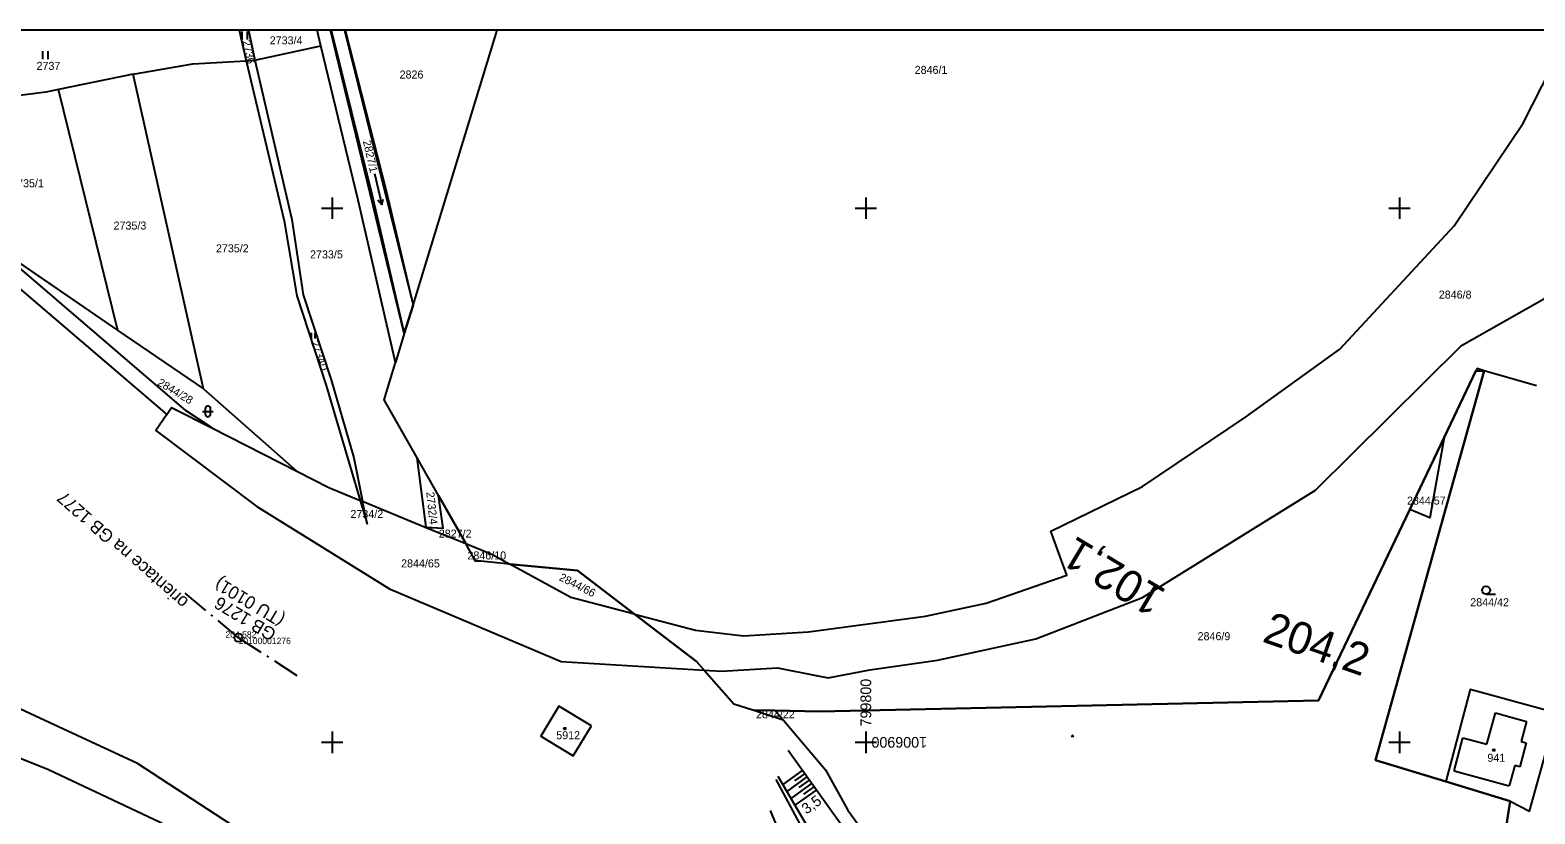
# Model space of a CAD drawing. Extents: x -800194 to -799078, y -1007177 to -1006597.
# Drawn here: x -799956.6 to -799674.6, y -1006913.4 to -1006766.6 of the extents above; entities that cross this region are included whole.
import ezdxf

# ---------------------------------------------------------------- set-up
doc = ezdxf.new("R2010")
doc.units = 0
for name, color, linetype in [('_Vrstva 7 - Přesunutá', 7, 'Continuous'), ('Legenda 1', 7, 'Continuous'), ('Ramove udaje', 7, 'Continuous'), ('Vrstva 48', 7, 'Continuous'), ('Vrstva 49', 7, 'Continuous'), ('Vrstva 53', 7, 'Continuous'), ('Vrstva 55', 7, 'Continuous'), ('Vrstva 56', 7, 'Continuous'), ('Vrstva 57', 7, 'Continuous'), ('Vrstva 58', 7, 'Continuous'), ('Vrstva 59', 7, 'Continuous'), ('Vrstva 60', 7, 'Continuous'), ('Vrstva 61', 7, 'Continuous'), ('Vrstva 63', 7, 'Continuous'), ('Vrstva 7', 7, 'Continuous')]:
    doc.layers.add(name, color=color, linetype=linetype)

msp = doc.modelspace()

# ---------------------------------------------------------------- linework, layer by layer
at = {"layer": 'Legenda 1'}
msp.add_lwpolyline([(-800193.4, -1007176.65), (-799312.4, -1007176.65), (-799312.4, -1006766.65), (-800193.4, -1006766.65)], close=True, dxfattribs=at)
at = {"layer": 'Ramove udaje'}
for p, q in [((-799900, -1006798), (-799900, -1006802)), ((-799800, -1006798), (-799800, -1006802)), ((-799700, -1006798), (-799700, -1006802)), ((-799902, -1006800), (-799900, -1006800)), ((-799900, -1006800), (-799898, -1006800)), ((-799802, -1006800), (-799800, -1006800)), ((-799800, -1006800), (-799798, -1006800)), ((-799702, -1006800), (-799700, -1006800)), ((-799700, -1006800), (-799698, -1006800)), ((-799900, -1006898), (-799900, -1006902)), ((-799800, -1006898), (-799800, -1006902)), ((-799700, -1006898), (-799700, -1006902)), ((-799902, -1006900), (-799900, -1006900)), ((-799900, -1006900), (-799898, -1006900)), ((-799802, -1006900), (-799800, -1006900)), ((-799800, -1006900), (-799798, -1006900)), ((-799702, -1006900), (-799700, -1006900)), ((-799700, -1006900), (-799698, -1006900))]:
    msp.add_line(p, q, dxfattribs=at)
at = {"layer": 'Vrstva 48'}
for p, q in [((-799811.93, -1006905.27), (-799815.58, -1006907.89)), ((-799811.05, -1006906.49), (-799814.82, -1006909.19)), ((-799811.49, -1006905.88), (-799813.35, -1006907.21)), ((-799810.18, -1006907.71), (-799814.06, -1006910.49)), ((-799809.31, -1006908.93), (-799813.3, -1006911.79)), ((-799810.62, -1006907.1), (-799812.53, -1006908.47)), ((-799809.74, -1006908.32), (-799811.71, -1006909.73))]:
    msp.add_line(p, q, dxfattribs=at)
at = {"layer": 'Vrstva 49'}
for p, q in [((-799761.44, -1006898.59), (-799761.08, -1006898.95)), ((-799761.44, -1006898.95), (-799761.08, -1006898.59))]:
    msp.add_line(p, q, dxfattribs=at)
for points in [[(-799779.16, -1006943.33), (-799796.9, -1006926.25), (-799814.58, -1006901.56)], [(-799816.48, -1006906.34), (-799809.08, -1006919.03), (-799804.33, -1006925.79)], [(-799804.93, -1006926.45), (-799809.53, -1006920.44), (-799816.79, -1006906.94)], [(-799817.93, -1006912.77), (-799815.19, -1006919.41), (-799811.75, -1006925.64), (-799808.12, -1006930.68), (-799809.62, -1006932.5), (-799809.74, -1006938.63), (-799809.9, -1006941.36)]]:
    msp.add_lwpolyline(points, dxfattribs=at)
at = {"layer": 'Vrstva 53'}
for points in [[(-799897.71, -1006766.65), (-799884.86, -1006818.16), (-799886.49, -1006823.47), (-799900.34, -1006766.65)], [(-799963.94, -1006806.68), (-799940.15, -1006822.89), (-799924.15, -1006833.79), (-799906.63, -1006849.24), (-799900.66, -1006852.28), (-799894.78, -1006854.69), (-799894.32, -1006854.87), (-799882.56, -1006859.69), (-799879.2, -1006859.87), (-799880.09, -1006853.81), (-799874.98, -1006862.8), (-799869.94, -1006864.86), (-799866.71, -1006866.63), (-799854.06, -1006867.84), (-799843.37, -1006876), (-799831.75, -1006884.86), (-799830.3, -1006886.5), (-799824.73, -1006892.78), (-799821.02, -1006893.98), (-799817.05, -1006894.06), (-799808.6, -1006894.22), (-799715.17, -1006892.15), (-799698.08, -1006856.38), (-799691.64, -1006842.91), (-799685.69, -1006830.46), (-799684.1, -1006830.47), (-799704.46, -1006903.31), (-799691.31, -1006907.33), (-799679.26, -1006911.01), (-799685.71, -1006952.41)], [(-799673.33, -1007118.14), (-799714.71, -1007110.97), (-799718.21, -1007083.69), (-799729.93, -1007087.54), (-799766.47, -1007095.84), (-799767.73, -1007094.8), (-799769.22, -1007093.56), (-799785.06, -1007080.42), (-799809.11, -1007056.81), (-799818.59, -1007034.4), (-799822.79, -1007029.13), (-799826.14, -1007024.13), (-799830.75, -1006966.73), (-799839.73, -1006961.33), (-799877.87, -1006942.17), (-799936.47, -1006903.99), (-799954.76, -1006895.45), (-799964.79, -1006890.84)]]:
    msp.add_lwpolyline(points, dxfattribs=at)
at = {"layer": 'Vrstva 55'}
for p, q in [((-799917.43, -1006766.65), (-799916.1, -1006772.38)), ((-799915.71, -1006766.65), (-799914.5, -1006772.29)), ((-799902.13, -1006769.59), (-799902.84, -1006766.65)), ((-799884.86, -1006818.16), (-799869.08, -1006766.65)), ((-799914.5, -1006772.29), (-799902.13, -1006769.59)), ((-799895.13, -1006798.48), (-799902.13, -1006769.59)), ((-799916.1, -1006772.38), (-799914.5, -1006772.29)), ((-799937.29, -1006774.9), (-799951.32, -1006777.78)), ((-799924.15, -1006833.79), (-799937.29, -1006774.9)), ((-799953.68, -1006778.26), (-799969.88, -1006780.37)), ((-799951.32, -1006777.78), (-799953.68, -1006778.26)), ((-799940.15, -1006822.89), (-799951.32, -1006777.78)), ((-799888.13, -1006828.86), (-799895.13, -1006798.48)), ((-799963.94, -1006806.68), (-799940.15, -1006822.89)), ((-799965.36, -1006809.25), (-799930.99, -1006838.59)), ((-799886.49, -1006823.47), (-799884.86, -1006818.16)), ((-799940.15, -1006822.89), (-799924.15, -1006833.79)), ((-799886.49, -1006823.47), (-799888.13, -1006828.86)), ((-799685.69, -1006830.46), (-799691.64, -1006842.91)), ((-799674.35, -1006833.26), (-799684.1, -1006830.47)), ((-799924.15, -1006833.79), (-799906.63, -1006849.24)), ((-799922.45, -1006841.18), (-799906.63, -1006849.24)), ((-799691.64, -1006842.91), (-799698.08, -1006856.38)), ((-799882.39, -1006859.7), (-799884.1, -1006846.76)), ((-799880.09, -1006853.81), (-799884.1, -1006846.76)), ((-799894.78, -1006854.69), (-799894.32, -1006854.87)), ((-799894.32, -1006854.87), (-799882.56, -1006859.69)), ((-799874.98, -1006862.8), (-799880.09, -1006853.81)), ((-799698.08, -1006856.38), (-799715.17, -1006892.15)), ((-799882.56, -1006859.69), (-799882.39, -1006859.7)), ((-799882.56, -1006859.69), (-799874.98, -1006862.8)), ((-799817.05, -1006894.06), (-799821.02, -1006893.98)), ((-799821.02, -1006893.98), (-799815.49, -1006895.78)), ((-799817.05, -1006894.06), (-799815.49, -1006895.78)), ((-799679.26, -1006911.01), (-799691.31, -1006907.33))]:
    msp.add_line(p, q, dxfattribs=at)
for points in [[(-799900.21, -1006766.65), (-799892.52, -1006797.61), (-799886.49, -1006823.47)], [(-799897.57, -1006766.65), (-799889.91, -1006796.74), (-799884.86, -1006818.16)], [(-799843.37, -1006876), (-799831.92, -1006878.98), (-799822.92, -1006880.05), (-799810.74, -1006879.32), (-799788.82, -1006876.36), (-799777.45, -1006873.96), (-799762.31, -1006868.73), (-799765.35, -1006860.47), (-799748.13, -1006852.13), (-799728.87, -1006839.09), (-799711.19, -1006826.38), (-799689.75, -1006803.29), (-799676.83, -1006784.06), (-799667.97, -1006766.65)], [(-799830.3, -1006886.5), (-799827.05, -1006886.7), (-799816.55, -1006886.06), (-799808.97, -1006887.52), (-799807.07, -1006887.91), (-799799.23, -1006886.45), (-799786.57, -1006884.64), (-799768.13, -1006880.63), (-799748.15, -1006872.9), (-799715.76, -1006852.76), (-799688.4, -1006825.67), (-799672.84, -1006816.93), (-799646.34, -1006766.65)], [(-799937.29, -1006774.9), (-799926.1, -1006772.97), (-799916.1, -1006772.38)], [(-799916.1, -1006772.38), (-799909.03, -1006802.36), (-799906.63, -1006816.4), (-799901.12, -1006833.19), (-799894.78, -1006854.69)], [(-799914.5, -1006772.29), (-799907.57, -1006802.13), (-799905.43, -1006816.22), (-799900.18, -1006832.12), (-799895.95, -1006846.75), (-799894.32, -1006854.87)], [(-799922.45, -1006841.18), (-799927.36, -1006837.92), (-799963.94, -1006806.68)], [(-799884.1, -1006846.76), (-799890.29, -1006835.89), (-799888.13, -1006828.86)], [(-799684.1, -1006830.47), (-799685.46, -1006829.98), (-799685.69, -1006830.46)], [(-799691.31, -1006907.33), (-799704.46, -1006903.31), (-799684.1, -1006830.47)], [(-799930.99, -1006838.59), (-799933.07, -1006841.6), (-799914.11, -1006855.86), (-799889.24, -1006871.28), (-799857.12, -1006884.86), (-799830.3, -1006886.5)], [(-799930.99, -1006838.59), (-799930.09, -1006837.28), (-799922.45, -1006841.18)], [(-799691.64, -1006842.91), (-799694.3, -1006857.94), (-799698.08, -1006856.38)], [(-799906.63, -1006849.24), (-799900.66, -1006852.28), (-799894.78, -1006854.69)], [(-799894.78, -1006854.69), (-799893.48, -1006859.09), (-799894.32, -1006854.87)], [(-799882.39, -1006859.7), (-799879.2, -1006859.87), (-799880.09, -1006853.81)], [(-799874.98, -1006862.8), (-799869.94, -1006864.86), (-799866.71, -1006866.63)], [(-799866.71, -1006866.63), (-799872.12, -1006866.11), (-799873.12, -1006866.06), (-799874.98, -1006862.8)], [(-799843.37, -1006876), (-799855.29, -1006872.89), (-799866.71, -1006866.63)], [(-799843.37, -1006876), (-799854.06, -1006867.84), (-799866.71, -1006866.63)], [(-799830.3, -1006886.5), (-799831.75, -1006884.86), (-799843.37, -1006876)], [(-799830.3, -1006886.5), (-799824.73, -1006892.78), (-799821.02, -1006893.98)], [(-799901.69, -1006974.63), (-799900.54, -1006973.82), (-799898.31, -1006947.43), (-799904.63, -1006933.89), (-799915, -1006924.46), (-799932.22, -1006915.03), (-799953.17, -1006905.18), (-799968.93, -1006898.86), (-799993.08, -1006892.39), (-800012.71, -1006890.11), (-800033.89, -1006890), (-800048.34, -1006892.35)], [(-799839.73, -1006961.33), (-799877.87, -1006942.17), (-799936.47, -1006903.99), (-799954.76, -1006895.45), (-799964.79, -1006890.84)], [(-799715.17, -1006892.15), (-799808.6, -1006894.22), (-799817.05, -1006894.06)], [(-799670.51, -1006894.51), (-799686.74, -1006890.11), (-799691.31, -1006907.33)], [(-799851.43, -1006896.91), (-799857.54, -1006893.23), (-799860.93, -1006898.86), (-799854.86, -1006902.52), (-799851.43, -1006896.91)], [(-799679.26, -1006911.01), (-799675.61, -1006912.91), (-799670.51, -1006894.51)], [(-799815.49, -1006895.78), (-799807.53, -1006905.17), (-799803.4, -1006912.69), (-799785.23, -1006937.71)], [(-799686.25, -1006963.73), (-799685.71, -1006952.41), (-799679.26, -1006911.01)]]:
    msp.add_lwpolyline(points, dxfattribs=at)
at = {"layer": 'Vrstva 56'}
for p, q in [((-799683.63, -1006900.36), (-799682.01, -1006894.5)), ((-799682.01, -1006894.5), (-799676.18, -1006896.08)), ((-799676.18, -1006896.08), (-799677.18, -1006899.82)), ((-799689.75, -1006905.35), (-799688.1, -1006899.14)), ((-799688.1, -1006899.14), (-799683.63, -1006900.36)), ((-799676.24, -1006900.07), (-799677.44, -1006904.58)), ((-799677.18, -1006899.82), (-799676.24, -1006900.07)), ((-799689.75, -1006905.35), (-799679.43, -1006908.15)), ((-799678.41, -1006904.32), (-799679.43, -1006908.15)), ((-799677.44, -1006904.58), (-799678.41, -1006904.32))]:
    msp.add_line(p, q, dxfattribs=at)
at = {"layer": 'Vrstva 58'}
for p, q in [((-799916.86, -1006768.43), (-799916.86, -1006766.93)), ((-799915.86, -1006768.43), (-799915.86, -1006766.93)), ((-799954.2, -1006772.07), (-799954.2, -1006770.57)), ((-799953.2, -1006772.07), (-799953.2, -1006770.57)), ((-799892.08, -1006793.51), (-799890.73, -1006799.35)), ((-799890.73, -1006799.35), (-799891.44, -1006798.51)), ((-799890.73, -1006799.35), (-799890.46, -1006798.29)), ((-799903.86, -1006824.36), (-799903.86, -1006823.35)), ((-799903.19, -1006824.36), (-799903.19, -1006823.35)), ((-799924.3, -1006838.04), (-799922.3, -1006838.04)), ((-799923.8, -1006837.54), (-799923.8, -1006838.54)), ((-799922.8, -1006838.54), (-799922.8, -1006837.54)), ((-799683.77, -1006872.27), (-799682.02, -1006872.27))]:
    msp.add_line(p, q, dxfattribs=at)
msp.add_circle((-799683.77, -1006871.52), 0.75, dxfattribs=at)
for centre, start, end in [((-799923.3, -1006837.54), 0, 180), ((-799923.3, -1006838.54), 180, 359.9879)]:
    msp.add_arc(centre, 0.5, start, end, dxfattribs=at)
at = {"layer": 'Vrstva 59'}
for centre in [(-799856.4, -1006897.43), (-799682.3, -1006901.44)]:
    msp.add_circle(centre, 0.175, dxfattribs=at)
at = {"layer": 'Vrstva 60'}
msp.add_line((-799917.56, -1006880.41), (-799917.56, -1006880.41), dxfattribs=at)
at = {"layer": 'Vrstva 63'}
for p, q in [((-799923.71, -1006875.3), (-799927.55, -1006872.1)), ((-799922.4, -1006876.38), (-799922.71, -1006876.13)), ((-799917.56, -1006880.41), (-799921.4, -1006877.21)), ((-799917.51, -1006880.44), (-799917.6, -1006880.38)), ((-799917.56, -1006880.41), (-799913.36, -1006883.13)), ((-799912.27, -1006883.83), (-799911.93, -1006884.05)), ((-799910.84, -1006884.76), (-799906.64, -1006887.47))]:
    msp.add_line(p, q, dxfattribs=at)
msp.add_circle((-799917.56, -1006880.41), 0.756, dxfattribs=at)

# ---------------------------------------------------------------- texts
at = {"layer": '_Vrstva 7 - Přesunutá'}
msp.add_text('204,2', height=6, rotation=340.8787, dxfattribs=at).set_placement((-799725.91, -1006881.09))
at = {"layer": 'Ramove udaje'}
for s, rotation, p in [('    799800', 90, (-799799, -1006900)), ('1006900    ', 180, (-799788.53, -1006899))]:
    msp.add_text(s, height=2, rotation=rotation, dxfattribs=at).set_placement(p)
at = {"layer": 'Vrstva 48'}
msp.add_text('3,5', height=2, rotation=35.6162, dxfattribs=at).set_placement((-799811.13, -1006913.54))
at = {"layer": 'Vrstva 57'}
for s, p in [('2733/4', (-799911.71, -1006769.31)), ('2737', (-799955.41, -1006774.09)), ('2846/1', (-799790.85, -1006774.84)), ('2826', (-799887.37, -1006775.71)), ('2735/1', (-799960.17, -1006796.07)), ('2735/3', (-799940.97, -1006803.99)), ('2735/2', (-799921.79, -1006808.25)), ('2733/5', (-799904.15, -1006809.39)), ('2846/8', (-799692.63, -1006816.92)), ('2844/57', (-799698.59, -1006855.49)), ('2734/2', (-799896.58, -1006858)), ('2827/2', (-799880.03, -1006861.68)), ('2846/10', (-799874.66, -1006865.76)), ('2844/65', (-799887.09, -1006867.25)), ('2844/42', (-799686.73, -1006874.52)), ('2846/9', (-799737.83, -1006880.88)), ('2844/22', (-799820.58, -1006895.51)), ('5912', (-799858.01, -1006899.42)), ('941', (-799683.52, -1006903.64))]:
    msp.add_text(s, height=1.5, dxfattribs=at).set_placement(p)
for s, rotation, p in [('2736', 282, (-799916.82, -1006768.71)), ('2827/1', 283, (-799894.26, -1006787.46)), ('2734/1', 289.2956, (-799904, -1006825.1)), ('2844/28', 329, (-799932.89, -1006833.03)), ('2732/4', 276, (-799882.37, -1006853.18)), ('2844/66', 333, (-799857.61, -1006869.57))]:
    msp.add_text(s, height=1.5, rotation=rotation, dxfattribs=at).set_placement(p)
at = {"layer": 'Vrstva 60'}
msp.add_text('10100001276', height=1.2, dxfattribs=at).set_placement((-799917.56, -1006881.61))
at = {"layer": 'Vrstva 61'}
msp.add_text('204.582', height=1.2, dxfattribs=at).set_placement((-799920, -1006880.41))
at = {"layer": 'Vrstva 63'}
for s, rotation, p in [('orientace na GB 1277', 138.6124, (-799926.77, -1006873.43)), ('(TU 0101)', 149.0426, (-799908.68, -1006876.43)), ('GB 1276', 149.0426, (-799910.27, -1006879.1))]:
    msp.add_text(s, height=2.4, rotation=rotation, dxfattribs=at).set_placement(p)
at = {"layer": 'Vrstva 7'}
msp.add_text('102,1', height=6, rotation=149.057, dxfattribs=at).set_placement((-799743.44, -1006871.61))

doc.saveas('drawing.dxf')
